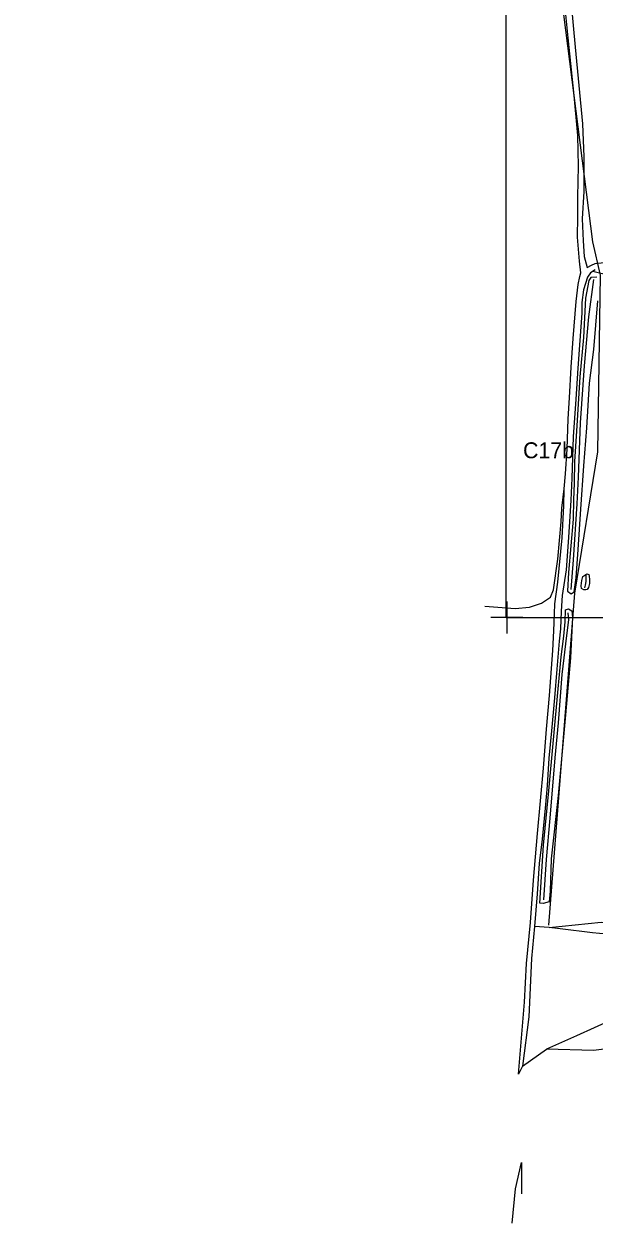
# Model space of a CAD drawing. Extents: x -478000 to -474772, y -1116940 to -1114124.
# Drawn here: x -478000.1 to -477821.2, y -1116939.9 to -1116563.9 of the extents above; entities that cross this region are included whole.
import ezdxf

# ---------------------------------------------------------------- set-up
doc = ezdxf.new("R2010")
doc.units = 0
for name, color, linetype in [('hrana_P', 7, 'Continuous'), ('L', 7, 'Continuous'), ('ObPÚ', 7, 'Continuous'), ('P', 7, 'Continuous'), ('popis', 7, 'Continuous'), ('razitko', 7, 'Continuous')]:
    doc.layers.add(name, color=color, linetype=linetype)

msp = doc.modelspace()

# ---------------------------------------------------------------- linework, layer by layer
at = {"layer": 'hrana_P'}
msp.add_lwpolyline([(-477848.81, -1116452.96), (-477008.1, -1116452.96), (-477008.1, -1116750.17), (-477848.81, -1116750.17)], close=True, dxfattribs=at)
at = {"layer": 'L'}
for p, q in [((-477822.83, -1116644.34), (-477823.89, -1116649.91)), ((-477822.25, -1116643.4), (-477822.83, -1116644.34)), ((-477820.37, -1116643.35), (-477822.25, -1116643.4)), ((-477823.89, -1116649.91), (-477824.6, -1116662.27)), ((-477821.26, -1116665.99), (-477820.05, -1116650.78)), ((-477824.6, -1116662.27), (-477825.69, -1116674.63)), ((-477822.67, -1116676.52), (-477821.26, -1116665.99)), ((-477825.69, -1116674.63), (-477826.73, -1116691.6)), ((-477823.45, -1116690.59), (-477822.67, -1116676.52)), ((-477826.73, -1116691.6), (-477827.35, -1116701.12)), ((-477824.42, -1116702.54), (-477823.45, -1116690.59)), ((-477827.35, -1116701.12), (-477827.47, -1116707.88)), ((-477825.36, -1116716.11), (-477824.42, -1116702.54)), ((-477827.47, -1116707.88), (-477827.69, -1116713.13)), ((-477827.69, -1116713.13), (-477827.82, -1116719.22)), ((-477826.18, -1116728.73), (-477825.36, -1116716.11)), ((-477827.82, -1116719.22), (-477829.27, -1116735.91)), ((-477826.84, -1116737.61), (-477826.18, -1116728.73)), ((-477829.27, -1116735.91), (-477829.52, -1116741.83)), ((-477827.47, -1116742.03), (-477826.84, -1116737.61)), ((-477825.33, -1116740.17), (-477825.05, -1116738.43)), ((-477825.05, -1116738.43), (-477824.75, -1116737.2)), ((-477824.75, -1116737.2), (-477823.47, -1116736.34)), ((-477823.47, -1116736.34), (-477822.91, -1116736.61)), ((-477822.62, -1116739.37), (-477822.99, -1116740.68)), ((-477822.91, -1116736.61), (-477822.73, -1116737.07)), ((-477822.73, -1116737.07), (-477822.68, -1116738.18)), ((-477822.68, -1116738.18), (-477822.62, -1116739.37)), ((-477829.52, -1116741.83), (-477828.44, -1116742.62)), ((-477828.44, -1116742.62), (-477827.47, -1116742.03)), ((-477825.13, -1116740.94), (-477825.33, -1116740.17)), ((-477824.46, -1116741.35), (-477825.13, -1116740.94)), ((-477823.84, -1116741.41), (-477824.46, -1116741.35)), ((-477823.36, -1116741.3), (-477823.84, -1116741.41)), ((-477822.99, -1116740.68), (-477823.36, -1116741.3)), ((-477830.3, -1116751.37), (-477830.23, -1116747.64)), ((-477830.23, -1116747.64), (-477829.24, -1116747.35)), ((-477829.24, -1116747.35), (-477828.26, -1116748)), ((-477827.95, -1116749.98), (-477828.62, -1116762.68)), ((-477828.26, -1116748), (-477827.95, -1116749.98)), ((-477830.77, -1116755.94), (-477830.3, -1116751.37)), ((-477831.53, -1116762.35), (-477830.77, -1116755.94)), ((-477832.47, -1116772.42), (-477831.53, -1116762.35)), ((-477828.62, -1116762.68), (-477830.18, -1116780.62)), ((-477835.39, -1116804.39), (-477832.47, -1116772.42)), ((-477830.18, -1116780.62), (-477832.53, -1116805.91)), ((-477837.11, -1116821.49), (-477835.39, -1116804.39)), ((-477832.53, -1116805.91), (-477834.72, -1116825.69)), ((-477838.29, -1116839.59), (-477837.11, -1116821.49)), ((-477834.72, -1116825.69), (-477835, -1116835.84)), ((-477835, -1116835.84), (-477835.35, -1116839.22)), ((-477837.17, -1116839.78), (-477838.29, -1116839.59)), ((-477835.35, -1116839.22), (-477837.17, -1116839.78)), ((-477844.01, -1116920.94), (-477844.05, -1116930.74))]:
    msp.add_line(p, q, dxfattribs=at)
for points in [[(-477826.29, -1116598.91), (-477827.52, -1116586.35), (-477829.32, -1116568.25), (-477830.8, -1116553.51), (-477832.83, -1116537.65), (-477834.92, -1116521.49), (-477836.68, -1116507.49), (-477837.67, -1116502.52), (-477839.32, -1116497.56), (-477841.12, -1116493.13), (-477846.66, -1116482.7), (-477850.21, -1116475.5), (-477853.63, -1116468.21), (-477857.37, -1116459.49), (-477858.89, -1116455.85)], [(-477857.3, -1116454.3), (-477851.7, -1116468.32), (-477847.03, -1116477.71), (-477839.24, -1116492.35), (-477837.62, -1116496.05), (-477836.21, -1116499.89), (-477834.67, -1116506.8), (-477833.82, -1116510.8), (-477832.45, -1116520.85), (-477830.65, -1116537.79), (-477828.53, -1116556.4), (-477827.16, -1116571.22), (-477824.85, -1116595.26), (-477824.46, -1116605.62)], [(-477831.27, -1116725.07), (-477830.77, -1116715.08), (-477830.59, -1116709.67), (-477830.18, -1116704.95), (-477829.63, -1116697.26), (-477829.32, -1116687.73), (-477828.92, -1116681.15), (-477828.46, -1116671.56), (-477827.77, -1116662.54), (-477826.8, -1116650.99), (-477826.24, -1116645.59), (-477825.71, -1116643.07), (-477825.41, -1116641.98), (-477825.76, -1116638.35), (-477826.39, -1116630.75), (-477826.36, -1116624.35), (-477826.36, -1116618.12), (-477826.08, -1116608.5), (-477826.29, -1116598.91)], [(-477824.46, -1116605.62), (-477824.4, -1116616.43), (-477824.96, -1116625.02), (-477824.64, -1116631.89), (-477824.33, -1116636.89), (-477823.39, -1116640.26), (-477822.04, -1116639.52)], [(-477820.86, -1116641.07), (-477822.31, -1116642.02), (-477823.27, -1116643.32), (-477824.55, -1116647.3), (-477825.02, -1116651.27), (-477825.05, -1116654.58), (-477825.67, -1116663.23), (-477826.37, -1116671.85), (-477826.95, -1116681.57), (-477827.8, -1116693.4), (-477828.24, -1116706.41), (-477828.5, -1116713.27), (-477828.93, -1116720.07), (-477829.36, -1116726.4), (-477829.99, -1116735.12), (-477831.22, -1116743.18), (-477831.52, -1116748.02), (-477831.77, -1116753.56), (-477832.18, -1116757.5), (-477832.87, -1116766.27), (-477833.64, -1116775.23), (-477834.54, -1116785.59), (-477835.38, -1116794.13), (-477835.9, -1116802.73), (-477836.6, -1116809.87), (-477837.48, -1116819.55), (-477838.41, -1116827.16), (-477839.04, -1116836.69), (-477839.87, -1116846.92), (-477840.87, -1116856.99), (-477841.74, -1116875.29), (-477843.66, -1116890.73), (-477844.99, -1116893.29), (-477843.04, -1116870.7), (-477842.44, -1116858.56), (-477841.17, -1116845.75), (-477840.19, -1116832.43), (-477838.93, -1116817.83), (-477837.07, -1116797.35), (-477836.19, -1116785.03), (-477835.18, -1116774.53), (-477834.14, -1116760.39), (-477833.82, -1116754.24), (-477833.6, -1116748.93), (-477833.58, -1116745.76), (-477832.64, -1116739), (-477831.27, -1116725.07)], [(-477822.04, -1116639.52), (-477820.9, -1116639.08), (-477817.12, -1116638.64), (-477804.89, -1116638.22), (-477790.56, -1116638.04), (-477775.67, -1116638.39), (-477759.07, -1116638.9), (-477743.41, -1116638.91), (-477727.38, -1116639.61), (-477703.51, -1116640.58), (-477689.09, -1116640.74), (-477662.5, -1116640.64)], [(-477619.52, -1116641.58), (-477631.23, -1116645.71), (-477649.97, -1116646.39), (-477673.38, -1116646.66), (-477700.23, -1116645.8), (-477732.12, -1116644.58), (-477759.79, -1116644.2), (-477782.63, -1116643.43), (-477804.35, -1116642.53), (-477816.49, -1116642.76), (-477821.58, -1116641.54)], [(-477821.38, -1116644.09), (-477822.96, -1116655.8), (-477824.3, -1116671.12), (-477825.64, -1116688.99), (-477826.24, -1116706.04), (-477826.61, -1116714.44), (-477827.83, -1116731.98), (-477828.54, -1116741.32)], [(-477824.18, -1116740.76), (-477823.89, -1116739.88), (-477823.74, -1116738.77), (-477823.71, -1116737.91), (-477823.69, -1116737.08), (-477823.68, -1116736.81)], [(-477835.34, -1116847.31), (-477818.99, -1116845.59), (-477800.5, -1116846.27), (-477788, -1116845.43), (-477777.55, -1116845.4), (-477773.75, -1116843.22), (-477771.77, -1116847.01), (-477769.07, -1116847.96), (-477766.24, -1116842.96), (-477762.74, -1116839.95), (-477762.75, -1116836.74), (-477764.62, -1116831.62), (-477763.32, -1116827.37), (-477756.12, -1116818.96), (-477748.17, -1116808.01), (-477739.72, -1116794.76), (-477724.35, -1116775.1), (-477708.92, -1116753.9), (-477700.31, -1116739.69)], [(-477836.95, -1116838.58), (-477836.11, -1116825.93), (-477834.99, -1116812.95), (-477833.46, -1116794.09), (-477832.38, -1116783.05), (-477831.25, -1116767.96), (-477829.78, -1116755.73), (-477829.1, -1116750.81), (-477829.34, -1116748.6)], [(-477667.09, -1116775.81), (-477678.38, -1116790.36), (-477691.45, -1116804), (-477702.45, -1116815.26), (-477715.33, -1116826.38), (-477731.42, -1116838.59), (-477746.66, -1116851.85), (-477756.44, -1116863.18), (-477764.52, -1116874.76), (-477767.83, -1116878.31), (-477773.14, -1116880.5), (-477781.51, -1116880.5), (-477807.96, -1116884.18), (-477821.44, -1116885.87), (-477836.17, -1116885.38)], [(-477767.12, -1116848.28), (-477770.68, -1116850.22), (-477773.1, -1116849.35), (-477775.4, -1116847.65), (-477783.76, -1116848.23), (-477797.03, -1116850.48), (-477808.51, -1116850.2), (-477821.73, -1116848.89), (-477831.9, -1116847.72), (-477835.34, -1116847.31)], [(-477773.39, -1116857.08), (-477778.78, -1116860.9), (-477786.96, -1116865.48), (-477806.98, -1116873.63), (-477815.69, -1116876.18), (-477826.78, -1116881.27), (-477836.17, -1116885.38)], [(-477846.92, -1116939.94), (-477845.85, -1116929.23), (-477844.01, -1116920.94)]]:
    msp.add_lwpolyline(points, dxfattribs=at)
at = {"layer": 'ObPÚ'}
msp.add_lwpolyline([(-477835.42, -1116846.57), (-477827.27, -1116742.43), (-477820.03, -1116698.07), (-477819.21, -1116642.72), (-477821.57, -1116632.3), (-477837.97, -1116504.33), (-477857.08, -1116470.65), (-477873.54, -1116443.03), (-477876.37, -1116437.54), (-477908.62, -1116376.53), (-477932.52, -1116347.32), (-477968.13, -1116341.56), (-477983.23, -1116329.55), (-478000.09, -1116315.61), (-477992.63, -1116266.4), (-477967.7, -1116217.95), (-477949.03, -1116186.01), (-477915.97, -1116136), (-477827.83, -1116006.6), (-477791.07, -1115962.29), (-477744.4, -1115881.63), (-477737.43, -1115839.5), (-477657.26, -1115725.45)], dxfattribs=at)
at = {"layer": 'P'}
for points in [[(-477855.51, -1116746.51), (-477845.97, -1116747.24), (-477841.45, -1116746.8), (-477837.74, -1116745.59), (-477834.85, -1116743.63), (-477833.95, -1116741.4), (-477832.56, -1116731.76), (-477831.59, -1116720.02), (-477831.31, -1116715.8), (-477830.59, -1116709.67)], [(-477835.34, -1116847.31), (-477839.87, -1116846.92)], [(-477843.66, -1116890.73), (-477836.17, -1116885.38)]]:
    msp.add_lwpolyline(points, dxfattribs=at)
at = {"layer": 'razitko'}
for p, q in [((-477848.58, -1116745.07), (-477848.57, -1116755.07)), ((-477848.58, -1116745.07), (-477848.57, -1116755.07)), ((-477848.58, -1116745.07), (-477848.57, -1116755.07)), ((-477848.58, -1116745.07), (-477848.57, -1116755.07)), ((-477848.58, -1116745.07), (-477848.57, -1116755.07)), ((-477848.58, -1116745.07), (-477848.57, -1116755.07)), ((-477848.58, -1116745.07), (-477848.57, -1116755.07)), ((-477848.58, -1116745.07), (-477848.57, -1116755.07)), ((-477848.58, -1116745.07), (-477848.57, -1116755.07)), ((-477848.58, -1116745.07), (-477848.57, -1116755.07)), ((-477848.58, -1116745.07), (-477848.57, -1116755.07)), ((-477848.58, -1116745.07), (-477848.57, -1116755.07)), ((-477848.58, -1116745.07), (-477848.57, -1116755.07)), ((-477848.58, -1116745.07), (-477848.57, -1116755.07)), ((-477843.58, -1116750.07), (-477853.58, -1116750.07))]:
    msp.add_line(p, q, dxfattribs=at)

# ---------------------------------------------------------------- texts
at = {"layer": 'popis'}
msp.add_text('C17b', height=5, rotation=360, dxfattribs=at).set_placement((-477843.51, -1116700.12))

doc.saveas('drawing.dxf')
